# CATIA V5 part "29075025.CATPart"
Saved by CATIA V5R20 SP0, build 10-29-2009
Part number: 29075025
Definition: NONE
Nomenclature: 29075025
Source: Unknown
Description: 29075025
Bounding box of the stored display mesh (mm): x -12.5 to 44.548, y -51.5 to 86.048, z -41.5 to 41.5
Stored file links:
  C:\Users\Utente\Desktop\IO LAVORO\3D X SITO CF\X SITO\PLASTICA\RF1\29075025.CATPart
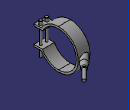
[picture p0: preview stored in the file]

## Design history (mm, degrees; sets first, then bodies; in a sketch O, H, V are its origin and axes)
Body1 "29075025" (main body)
  Solid1: solid without history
